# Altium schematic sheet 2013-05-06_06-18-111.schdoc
size 247 x 165 mm; SheetNumber: 1; SheetTotal: 1
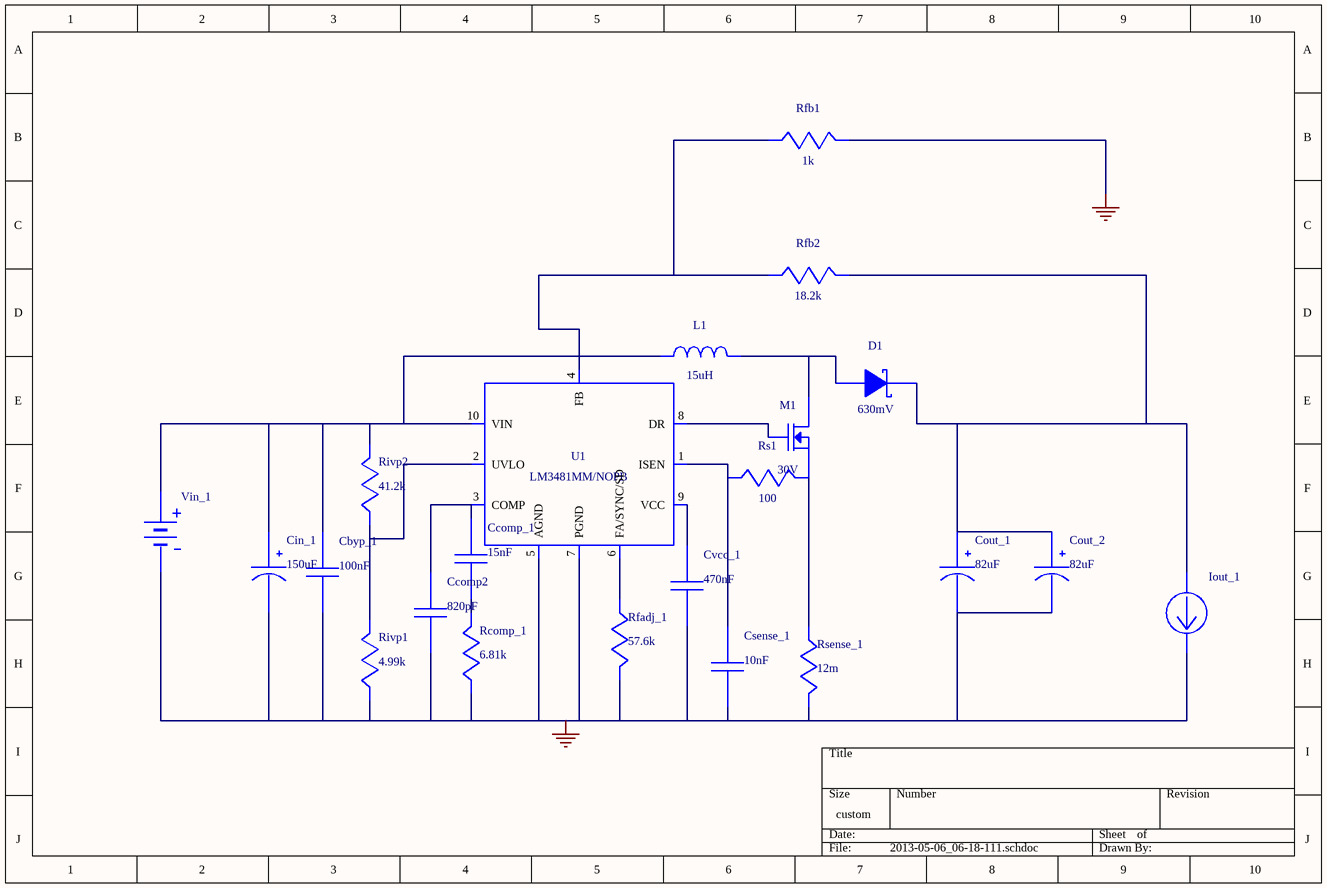
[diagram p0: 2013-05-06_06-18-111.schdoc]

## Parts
Cbyp_1  value 100nF  (hidden comment: 08053C104KAT2A)
Ccomp2  value 820pF  (hidden comment: CC0805KRX7R9BB821)
Ccomp_1  value 15nF  (hidden comment: CC0805KRX7R9BB153)
Cin_1  value 150uF  (hidden comment: UUD1E151MNL1GS)
Cout_1  value 82uF  (hidden comment: GENERIC_CAP_POLARIZED)
Cout_2  value 82uF  (hidden comment: GENERIC_CAP_POLARIZED)
Csense_1  value 10nF  (hidden comment: GRM216R71H103KA01D)
Cvcc_1  value 470nF  (hidden comment: GRM155C80J474KE19D)
D1  value 630mV  (hidden comment: MBRB1635PBF)
Iout_1  WB_CURRENT_LOAD  (value not drawn)
L1  value 15uH  (hidden comment: XAL1010-153MEB)
M1  value 30V  (hidden comment: CSD17308Q3)
Rcomp_1  value 6.81k  (hidden comment: CRCW04026K81FKED)
Rfadj_1  value 57.6k  (hidden comment: CRCW040257K6FKED)
Rfb1  value 1k  (hidden comment: CRCW04021K00FKED)
Rfb2  value 18.2k  (hidden comment: CRCW040218K2FKED)
Rivp1  value 4.99k  (hidden comment: CRCW04024K99FKED)
Rivp2  value 41.2k  (hidden comment: CRCW040241K2FKED)
Rs1  value 100  (hidden comment: CRCW0402100RFKED)
Rsense_1  value 12m  (hidden comment: CSR1206FK12L0)
U1  LM3481MM/NOPB
Vin_1  WB_BATTERY  (value not drawn)

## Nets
0: Cbyp_1.2 Ccomp2.2 Cin_1.2(-) Cout_1.2(-) Cout_2.2(-) Csense_1.2 Cvcc_1.2 Iout_1.2(-) Rcomp_1.2 Rfadj_1.1 Rfb1.1 Rivp1.2 Rsense_1.1 U1.5(AGND) U1.7(PGND) Vin_1.2(-)
NetCbyp_1_1: Cbyp_1.1 Cin_1.1(+) L1.2 Rivp2.1 U1.10(VIN) Vin_1.1(+)
NetCcomp2_1: Ccomp2.1 Ccomp_1.1 U1.3(COMP)
NetCcomp_1_2: Ccomp_1.2 Rcomp_1.1
NetCout_1_1: Cout_1.1(+) Cout_2.1(+) D1.4(K) Iout_1.1(+) Rfb2.1
NetCsense_1_1: Csense_1.1 Rs1.2 U1.1(ISEN)
NetCvcc_1_1: Cvcc_1.1 U1.9(VCC)
NetD1_3: D1.3(A) L1.1 M1.5(Drain) M1.6(Drain) M1.7(Drain) M1.8(Drain)
NetM1_1: M1.1(Source) M1.2(Source) M1.3(Source) Rs1.1 Rsense_1.2
NetM1_4: M1.4(Gate) U1.8(DR)
NetRfadj_1_2: Rfadj_1.2 U1.6(FA/SYNC/SD)
NetRfb1_2: Rfb1.2 Rfb2.2 U1.4(FB)
NetRivp1_1: Rivp1.1 Rivp2.2 U1.2(UVLO)

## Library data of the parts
Cbyp_1 = 08053C104KAT2A: Manufacturer Name: AVX
Ccomp2 = CC0805KRX7R9BB821: CC0805KRX7R9BB82; Manufacturer Name: Yageo America
Ccomp_1 = CC0805KRX7R9BB153: CC0805KRX7R9BB15; Manufacturer Name: Yageo America
Cin_1 = UUD1E151MNL1GS: Manufacturer Name: Nichicon
Cout_1 Cout_2 = GENERIC_CAP_POLARIZED: 35SVPF82M; Manufacturer Name: Sanyo
Csense_1 = GRM216R71H103KA01D: GRM216R71H103KA0; Manufacturer Name: MuRata
Cvcc_1 = GRM155C80J474KE19D: GRM155C80J474KE1; Manufacturer Name: MuRata
D1 = MBRB1635PBF: Manufacturer Name: Vishay-Semiconductor
Iout_1 = WB_CURRENT_LOAD: Value: UNLISTED
L1 = XAL1010-153MEB: Manufacturer Name: Coilcraft
M1 = CSD17308Q3: Manufacturer Name: Texas Instruments
Rcomp_1 = CRCW04026K81FKED: Manufacturer Name: Vishay-Dale
Rfadj_1 = CRCW040257K6FKED: Manufacturer Name: Vishay-Dale
Rfb1 = CRCW04021K00FKED: Manufacturer Name: Vishay-Dale
Rfb2 = CRCW040218K2FKED: Manufacturer Name: Vishay-Dale
Rivp1 = CRCW04024K99FKED: Manufacturer Name: Vishay-Dale
Rivp2 = CRCW040241K2FKED: Manufacturer Name: Vishay-Dale
Rs1 = CRCW0402100RFKED: Manufacturer Name: Vishay-Dale
Rsense_1 = CSR1206FK12L0: Manufacturer Name: Stackpole Electronics Inc
U1 = LM3481MM/NOPB: Manufacturer Name: Texas Instruments; Value: UNLISTED
Vin_1 = WB_BATTERY: Value: UNLISTED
